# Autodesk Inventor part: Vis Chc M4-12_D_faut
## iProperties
Created: 2011-10
Part Number: Vis Chc M4-12_D_faut
Document SubType Name: Modeling
Designer: Bruno
Author: Bruno
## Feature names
1. Base1
